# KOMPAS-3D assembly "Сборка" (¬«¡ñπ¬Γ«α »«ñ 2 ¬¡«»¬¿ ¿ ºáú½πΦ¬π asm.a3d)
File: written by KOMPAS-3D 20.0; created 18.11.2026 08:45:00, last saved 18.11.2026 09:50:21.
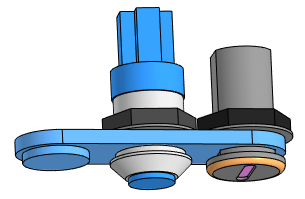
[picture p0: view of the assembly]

Document properties: Полное имя файла: D:\RicWork\Project-EPS32\box_compas\сборки компонентов\кондуктор под 2 кнопки и заглушку asm.a3d

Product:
- Part/product: Сборка
    Масса: 0.0506114
  - Component [detail]: Деталь  | Масса: 0.017827; source file: ..\разъемы\USB-C_Type-C 6pin.m3d
  - Component [assembly]: Сборка  | Масса: 0.023656; source file: ..\переключатели и кнопки\button_momentary self-reset 12 asm.a3d
  - Component [detail]: Деталь  | Масса: 0.00912843; source file: ..\корпус\кондуктор под 2 кнопки и заглушку.m3d

Referenced files in D:\RicWork\Project-EPS32\box_compas\корпус\: кондуктор под 2 кнопки и заглушку.m3d
Referenced files in D:\RicWork\Project-EPS32\box_compas\переключатели и кнопки\: button_momentary self-reset 12 asm.a3d
Referenced files in D:\RicWork\Project-EPS32\box_compas\разъемы\: USB-C_Type-C 6pin.m3d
